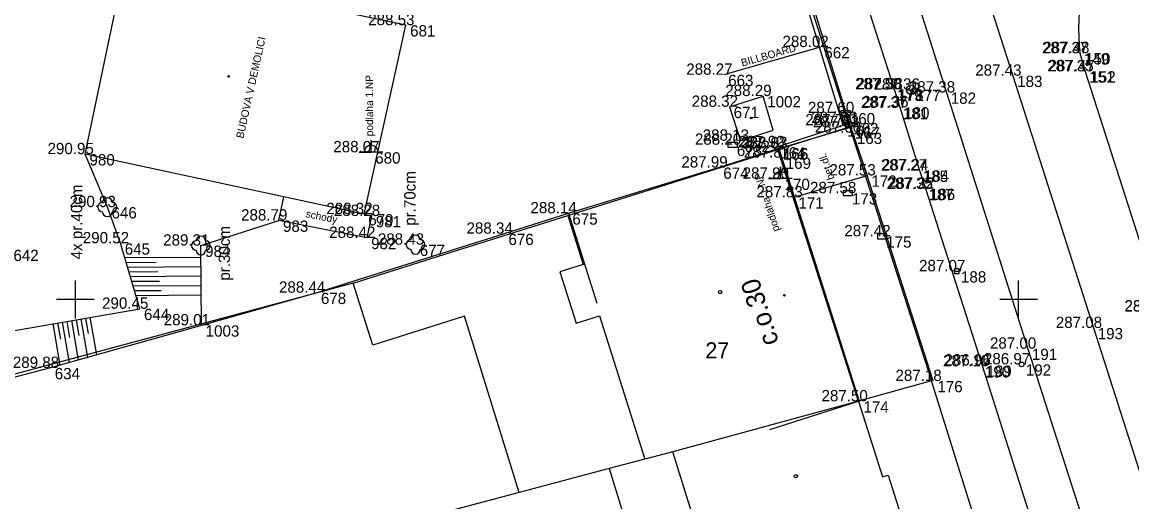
# Model space of a CAD drawing. Extents: x -599970 to -599524, y -1154772 to -1154457.
# Drawn here: x -599702.8 to -599644, y -1154660.7 to -1154635.3 of the extents above; entities that cross this region are included whole.
import ezdxf

# ---------------------------------------------------------------- set-up
doc = ezdxf.new("R2010")
doc.units = 0
for name, color, linetype in [('Z-BUDOVY', 7, 'Continuous'), ('Z-ELEKTRICKE SKRINE LAMPY', 7, 'Continuous'), ('Z-KANALIZACNI SACHTY VPUSTI', 7, 'Continuous'), ('Z-KATASTRALNI MAPA', 7, 'Continuous'), ('Z-KRIZKY CTVERCOVE SITE', 7, 'Continuous'), ('Z-ORIENTACNI A POPISNA CISLA', 7, 'Continuous'), ('Z-PLOT BETONOVY', 7, 'Continuous'), ('Z-PLOT DRATENY', 7, 'Continuous'), ('Z-PLYNOVODNI SOUPATA HUP', 7, 'Continuous'), ('Z-PODROBNE BODY', 7, 'Continuous'), ('Z-PODROBNE BODY-CISLO', 7, 'Continuous'), ('Z-PODROBNE BODY-VYSKA', 7, 'Continuous'), ('Z-POPISY OBJEKTU A ZPEVNENYCH PLOCH', 7, 'Continuous'), ('Z-PRUMERY KMENU STROMU', 7, 'Continuous'), ('Z-SCHODY', 7, 'Continuous'), ('Z-SDELOVACI VEDENI A OBJEKTY', 7, 'Continuous'), ('Z-SRAFOVANI SVAHU', 7, 'Continuous'), ('Z-STROMY ZNACKY KULTUR', 7, 'Continuous'), ('Z-TERENNI HRANY PATY', 7, 'Continuous'), ('Z-VODOROVNE ZNACENI', 7, 'Continuous'), ('Z-VODOVODNI SACHTY SOUPATA HYDRANTY', 7, 'Continuous'), ('Z-VSTUPY VJEZDY', 7, 'Continuous'), ('Z-VYSKOVE BODY', 7, 'Continuous'), ('Z-ZPEVNENE PLOCHY', 7, 'Continuous')]:
    doc.layers.add(name, color=color, linetype=linetype)

msp = doc.modelspace()

# ---------------------------------------------------------------- linework, layer by layer
at = {"layer": 'Z-BUDOVY'}
for p, q in [((-599665.33, -1154639.78), (-599663.55, -1154639.21)), ((-599662.72, -1154641.99), (-599665.88, -1154643)), ((-599665.88, -1154643), (-599673.88, -1154645.43)), ((-599672.34, -1154650.21), (-599673.84, -1154645.44)), ((-599658.45, -1154655.4), (-599663.21, -1154656.92))]:
    msp.add_line(p, q, dxfattribs=at)
for points in [[(-599684.7, -1154645.47), (-599699.48, -1154642.29), (-599697.4, -1154632.32)], [(-599684.7, -1154645.47), (-599682.48, -1154635.45), (-599697.4, -1154632.32)], [(-599664.75, -1154641.58), (-599663.01, -1154641.02), (-599663.55, -1154639.21)], [(-599665.33, -1154639.78), (-599664.75, -1154641.58)], [(-599662.72, -1154641.99), (-599658.45, -1154655.4)]]:
    msp.add_lwpolyline(points, dxfattribs=at)
at = {"layer": 'Z-ELEKTRICKE SKRINE LAMPY'}
for points in [[(-599665.41, -1154641.915), (-599664.91, -1154641.915), (-599664.91, -1154641.665), (-599665.41, -1154641.665)], [(-599659.31, -1154644.485), (-599658.81, -1154644.485), (-599658.81, -1154644.235), (-599659.31, -1154644.235)]]:
    msp.add_lwpolyline(points, close=True, dxfattribs=at)
at = {"layer": 'Z-KANALIZACNI SACHTY VPUSTI'}
msp.add_line((-599653.405, -1154648.5), (-599653.155, -1154648.5), dxfattribs=at)
msp.add_lwpolyline([(-599653.405, -1154648.625), (-599653.155, -1154648.625), (-599653.155, -1154648.375), (-599653.405, -1154648.375)], close=True, dxfattribs=at)
msp.add_circle((-599655.69, -1154638.87), 0.25, dxfattribs=at)
at = {"layer": 'Z-KATASTRALNI MAPA'}
for p, q in [((-599658.96, -1154640.84), (-599673.37, -1154595.74)), ((-599658.96, -1154640.84), (-599654.62, -1154654.32)), ((-599658.49, -1154655.39), (-599662.77, -1154642.04)), ((-599673.9, -1154645.54), (-599673.08, -1154648.14)), ((-599673.08, -1154648.14), (-599674.32, -1154648.54)), ((-599674.32, -1154648.54), (-599673.46, -1154651.26)), ((-599685.27, -1154649.13), (-599725.18, -1154659.85)), ((-599673.46, -1154651.26), (-599672.22, -1154650.87)), ((-599672.22, -1154650.87), (-599669.81, -1154658.47)), ((-599654.62, -1154654.32), (-599658.49, -1154655.39)), ((-599652.49, -1154661.15), (-599654.62, -1154654.32)), ((-599658.49, -1154655.39), (-599657.21, -1154659.4)), ((-599666.06, -1154665.39), (-599668.33, -1154658.07)), ((-599671.71, -1154658.97), (-599676.48, -1154660.24)), ((-599671.71, -1154658.97), (-599669.38, -1154666.43)), ((-599657.21, -1154659.4), (-599656.92, -1154659.31)), ((-599656.92, -1154659.31), (-599655.99, -1154662.24)), ((-599676.48, -1154660.24), (-599683.62, -1154662.13))]:
    msp.add_line(p, q, dxfattribs=at)
for points in [[(-599685.27, -1154649.13), (-599680.41, -1154647.6), (-599673.9, -1154645.54), (-599662.77, -1154642.04), (-599658.96, -1154640.84)], [(-599676.48, -1154660.24), (-599679.37, -1154650.89), (-599684.23, -1154652.42), (-599685.27, -1154649.13)], [(-599658.49, -1154655.39), (-599668.33, -1154658.07), (-599669.81, -1154658.47), (-599671.71, -1154658.97)]]:
    msp.add_lwpolyline(points, dxfattribs=at)
for centre in [(-599665.823, -1154649.61), (-599661.813, -1154659.37)]:
    msp.add_circle(centre, 0.0875, dxfattribs=at)
at = {"layer": 'Z-KRIZKY CTVERCOVE SITE'}
for p, q in [((-599700, -1154651), (-599700, -1154649)), ((-599650, -1154651), (-599650, -1154649)), ((-599699, -1154650), (-599701, -1154650)), ((-599649, -1154650), (-599651, -1154650))]:
    msp.add_line(p, q, dxfattribs=at)
at = {"layer": 'Z-PLOT BETONOVY'}
msp.add_lwpolyline([(-599673.88, -1154645.43), (-599677.27, -1154646.51), (-599687.21, -1154649.64)], dxfattribs=at)
at = {"layer": 'Z-PLOT DRATENY'}
for points in [[(-599662.86, -1154641.92), (-599659.31, -1154640.76), (-599663.16, -1154628.02), (-599666.48, -1154617.56)], [(-599659.31, -1154640.76), (-599658.99, -1154640.64), (-599658.91, -1154640.86), (-599658.8, -1154641.15)], [(-599654.53, -1154654.32), (-599658.03, -1154643.42)], [(-599687.21, -1154649.64), (-599693.32, -1154651.37), (-599701.32, -1154653.63), (-599705.77, -1154654.79), (-599712.31, -1154656.66), (-599717.12, -1154657.86), (-599722.32, -1154659.26), (-599725.96, -1154660.31)]]:
    msp.add_lwpolyline(points, dxfattribs=at)
at = {"layer": 'Z-PLYNOVODNI SOUPATA HUP'}
msp.add_lwpolyline([(-599657.49, -1154646.775), (-599656.99, -1154646.775), (-599656.99, -1154646.525), (-599657.49, -1154646.525)], close=True, dxfattribs=at)
at = {"layer": 'Z-PODROBNE BODY'}
for p, q in [((-599682.48, -1154635.45), (-599682.48, -1154635.45)), ((-599660.52, -1154636.61), (-599660.52, -1154636.61)), ((-599646.76, -1154636.94), (-599646.76, -1154636.94)), ((-599646.7, -1154636.93), (-599646.7, -1154636.93)), ((-599665.62, -1154638.08), (-599665.62, -1154638.08)), ((-599650.3, -1154638.13), (-599650.3, -1154638.13)), ((-599646.48, -1154637.9), (-599646.48, -1154637.9)), ((-599646.42, -1154637.89), (-599646.42, -1154637.89)), ((-599656.67, -1154638.85), (-599656.67, -1154638.85)), ((-599656.6, -1154638.85), (-599656.6, -1154638.85)), ((-599655.69, -1154638.87), (-599655.69, -1154638.87)), ((-599663.55, -1154639.21), (-599663.55, -1154639.21)), ((-599653.82, -1154639.02), (-599653.82, -1154639.02)), ((-599665.33, -1154639.78), (-599665.33, -1154639.78)), ((-599656.36, -1154639.84), (-599656.36, -1154639.84)), ((-599656.29, -1154639.8), (-599656.29, -1154639.8)), ((-599659.17, -1154640.11), (-599659.17, -1154640.11)), ((-599658.99, -1154640.64), (-599658.99, -1154640.64)), ((-599659.31, -1154640.76), (-599659.31, -1154640.76)), ((-599658.91, -1154640.86), (-599658.91, -1154640.86)), ((-599658.8, -1154641.15), (-599658.8, -1154641.15)), ((-599665.16, -1154641.79), (-599665.16, -1154641.79)), ((-599664.75, -1154641.58), (-599664.75, -1154641.58)), ((-599699.48, -1154642.29), (-599699.48, -1154642.29)), ((-599684.33, -1154642.19), (-599684.33, -1154642.19)), ((-599662.86, -1154641.92), (-599662.86, -1154641.92)), ((-599662.72, -1154641.99), (-599662.72, -1154641.99)), ((-599662.71, -1154641.97), (-599662.71, -1154641.97)), ((-599665.88, -1154643), (-599665.88, -1154643)), ((-599662.57, -1154642.47), (-599662.57, -1154642.47)), ((-599662.63, -1154643.59), (-599662.63, -1154643.59)), ((-599658.03, -1154643.42), (-599658.03, -1154643.42)), ((-599655.3, -1154643.16), (-599655.3, -1154643.16)), ((-599655.25, -1154643.15), (-599655.25, -1154643.15)), ((-599655, -1154644.14), (-599655, -1154644.14)), ((-599654.93, -1154644.12), (-599654.93, -1154644.12)), ((-599661.9, -1154644.58), (-599661.9, -1154644.58)), ((-599659.06, -1154644.36), (-599659.06, -1154644.36)), ((-599698.31, -1154645.1), (-599698.31, -1154645.1)), ((-599689.22, -1154645.81), (-599689.22, -1154645.81)), ((-599684.7, -1154645.47), (-599684.7, -1154645.47)), ((-599684.3, -1154645.57), (-599684.3, -1154645.57)), ((-599673.88, -1154645.43), (-599673.88, -1154645.43)), ((-599677.27, -1154646.51), (-599677.27, -1154646.51)), ((-599697.61, -1154647.02), (-599697.61, -1154647.02)), ((-599693.35, -1154647.14), (-599693.35, -1154647.14)), ((-599684.55, -1154646.73), (-599684.55, -1154646.73)), ((-599681.97, -1154647.09), (-599681.97, -1154647.09)), ((-599657.24, -1154646.65), (-599657.24, -1154646.65)), ((-599653.28, -1154648.5), (-599653.28, -1154648.5)), ((-599687.21, -1154649.64), (-599687.21, -1154649.64)), ((-599696.59, -1154650.49), (-599696.59, -1154650.49)), ((-599693.32, -1154651.37), (-599693.32, -1154651.37)), ((-599646.03, -1154651.51), (-599646.03, -1154651.51)), ((-599649.52, -1154652.61), (-599649.52, -1154652.61)), ((-599652.01, -1154653.54), (-599652.01, -1154653.54)), ((-599651.93, -1154653.5), (-599651.93, -1154653.5)), ((-599649.84, -1154653.44), (-599649.84, -1154653.44)), ((-599701.32, -1154653.63), (-599701.32, -1154653.63)), ((-599654.53, -1154654.32), (-599654.53, -1154654.32)), ((-599658.45, -1154655.4), (-599658.45, -1154655.4))]:
    msp.add_line(p, q, dxfattribs=at)
at = {"layer": 'Z-SCHODY'}
msp.add_lwpolyline([(-599684.7, -1154645.47), (-599684.3, -1154645.57), (-599684.55, -1154646.73), (-599689.22, -1154645.81), (-599688.96, -1154644.55)], dxfattribs=at)
for centre in [(-599691.88, -1154638.17), (-599664.18, -1154640.37), (-599662.42, -1154649.78)]:
    msp.add_circle(centre, 0.0438, dxfattribs=at)
at = {"layer": 'Z-SDELOVACI VEDENI A OBJEKTY'}
msp.add_lwpolyline([(-599659.42, -1154640.235), (-599658.92, -1154640.235), (-599658.92, -1154639.985), (-599659.42, -1154639.985)], close=True, dxfattribs=at)
at = {"layer": 'Z-SRAFOVANI SVAHU'}
for points in [[(-599697.39, -1154647.78), (-599693.35, -1154647.75)], [(-599697.31, -1154648.03), (-599695.72, -1154648.02)], [(-599697.24, -1154648.28), (-599693.34, -1154648.25)], [(-599697.17, -1154648.53), (-599695.63, -1154648.52)], [(-599697.09, -1154648.78), (-599693.34, -1154648.75)], [(-599697.02, -1154649.03), (-599695.55, -1154649.02)], [(-599696.95, -1154649.28), (-599693.33, -1154649.25)], [(-599696.87, -1154649.53), (-599695.46, -1154649.52)], [(-599696.8, -1154649.78), (-599693.33, -1154649.75)], [(-599700.95, -1154651.24), (-599700.8, -1154652.11)], [(-599700.71, -1154651.2), (-599700.33, -1154653.35)], [(-599700.46, -1154651.16), (-599700.31, -1154652.01)], [(-599700.21, -1154651.11), (-599699.85, -1154653.21)], [(-599699.97, -1154651.07), (-599699.82, -1154651.9)], [(-599699.72, -1154651.03), (-599699.37, -1154653.08)], [(-599699.47, -1154650.99), (-599699.33, -1154651.8)], [(-599699.23, -1154650.94), (-599698.88, -1154652.94)], [(-599701.2, -1154651.28), (-599700.82, -1154653.49)]]:
    msp.add_lwpolyline(points, dxfattribs=at)
at = {"layer": 'Z-STROMY ZNACKY KULTUR'}
for centre in [(-599698.31, -1154645.1), (-599693.35, -1154647.14), (-599681.97, -1154647.09)]:
    msp.add_circle(centre, 0.00025, dxfattribs=at)
for centre, start, end in [((-599698.31, -1154644.85), 0, 179.99999), ((-599698.56, -1154645.1), 89.99999, 269.99999), ((-599698.31, -1154645.35), 179.99999, 359.99999), ((-599698.06, -1154645.1), 270, 89.99999), ((-599693.6, -1154647.14), 89.99999, 269.99999), ((-599693.35, -1154646.89), 0, 179.99999), ((-599693.1, -1154647.14), 270, 89.99999), ((-599682.22, -1154647.09), 89.99999, 269.99999), ((-599681.97, -1154646.84), 0, 179.99999), ((-599681.72, -1154647.09), 270, 89.99999), ((-599693.35, -1154647.39), 179.99999, 359.99999), ((-599681.97, -1154647.34), 179.99999, 359.99999)]:
    msp.add_arc(centre, 0.25, start, end, dxfattribs=at)
at = {"layer": 'Z-TERENNI HRANY PATY'}
for points in [[(-599706.85, -1154650.78), (-599704.37, -1154651.83), (-599696.59, -1154650.49), (-599697.61, -1154647.02), (-599698.31, -1154645.1), (-599699.48, -1154642.29)], [(-599693.32, -1154651.37), (-599693.35, -1154647.14), (-599689.22, -1154645.81)]]:
    msp.add_lwpolyline(points, dxfattribs=at)
at = {"layer": 'Z-VODOROVNE ZNACENI'}
for points in [[(-599694.02, -1154499.99), (-599689.54, -1154514.32), (-599685.46, -1154527.42), (-599683.24, -1154534.53), (-599677.91, -1154551.43), (-599673.26, -1154566.04), (-599670.15, -1154575.91), (-599664.69, -1154593.08), (-599661.63, -1154602.65), (-599657.71, -1154615.01), (-599654.33, -1154625.58), (-599650.3, -1154638.13), (-599646.03, -1154651.51), (-599641.58, -1154665.41), (-599629.85, -1154702.06), (-599625.38, -1154716.06)], [(-599697.63, -1154501.15), (-599693.46, -1154514.34), (-599689.12, -1154528.02), (-599685.9, -1154538.22), (-599681.17, -1154553.13), (-599676.65, -1154567.39), (-599673.59, -1154577), (-599671.31, -1154584.14), (-599668.11, -1154594.2), (-599666.34, -1154599.75), (-599661.15, -1154616.02), (-599657.79, -1154626.57), (-599653.82, -1154639.02), (-599649.52, -1154652.61), (-599645.03, -1154666.6), (-599639.28, -1154684.62), (-599637.35, -1154690.63), (-599633.4, -1154703.39)]]:
    msp.add_lwpolyline(points, dxfattribs=at)
at = {"layer": 'Z-VODOVODNI SACHTY SOUPATA HYDRANTY'}
msp.add_circle((-599649.84, -1154653.44), 0.125, dxfattribs=at)
at = {"layer": 'Z-VSTUPY VJEZDY'}
for points in [[(-599658.8, -1154641.15), (-599658.03, -1154643.42)], [(-599662.57, -1154642.47), (-599661.9, -1154644.58)]]:
    msp.add_lwpolyline(points, dxfattribs=at)
at = {"layer": 'Z-VYSKOVE BODY'}
for p, q in [((-599684.33, -1154641.565), (-599684.33, -1154641.815)), ((-599684.33, -1154641.815), (-599684.33, -1154641.565)), ((-599684.33, -1154642.19), (-599684.33, -1154641.565)), ((-599684.33, -1154641.565), (-599684.33, -1154641.815)), ((-599683.705, -1154642.19), (-599684.955, -1154642.19)), ((-599684.955, -1154642.19), (-599684.33, -1154642.19)), ((-599683.705, -1154642.19), (-599684.33, -1154642.19)), ((-599662.63, -1154642.965), (-599662.63, -1154643.215)), ((-599662.63, -1154643.215), (-599662.63, -1154642.965)), ((-599662.63, -1154643.59), (-599662.63, -1154642.965)), ((-599662.63, -1154642.965), (-599662.63, -1154643.215)), ((-599662.005, -1154643.59), (-599663.255, -1154643.59)), ((-599663.255, -1154643.59), (-599662.63, -1154643.59)), ((-599662.005, -1154643.59), (-599662.63, -1154643.59))]:
    msp.add_line(p, q, dxfattribs=at)
for centre, start, end in [((-599684.33, -1154642.19), 89.99999, 179.99999), ((-599684.33, -1154642.19), 0, 89.99999), ((-599662.63, -1154643.59), 89.99999, 179.99999), ((-599662.63, -1154643.59), 0, 89.99999)]:
    msp.add_arc(centre, 0.375, start, end, dxfattribs=at)
at = {"layer": 'Z-ZPEVNENE PLOCHY'}
for points in [[(-599672.4, -1154589.48), (-599670.73, -1154594.81), (-599667.36, -1154605.26), (-599665.4, -1154611.41), (-599665.09, -1154612.38), (-599663.59, -1154616.97), (-599663.32, -1154617.94), (-599660.4, -1154627.02), (-599656.6, -1154638.85), (-599656.29, -1154639.8), (-599655.25, -1154643.15), (-599654.93, -1154644.12), (-599651.93, -1154653.5), (-599647.41, -1154667.76), (-599641.59, -1154686.01), (-599637.45, -1154690.75), (-599637.27, -1154691.05), (-599637.22, -1154691.51), (-599636.57, -1154701.7), (-599631.18, -1154718.34)], [(-599666.48, -1154617.56), (-599666.25, -1154617.44), (-599662.9, -1154627.92), (-599658.99, -1154640.64)], [(-599660.52, -1154636.61), (-599665.62, -1154638.08)], [(-599646.76, -1154636.94), (-599646.48, -1154637.9), (-599642.39, -1154650.64), (-599638.05, -1154664.15), (-599632.16, -1154682.64), (-599630.36, -1154688.43), (-599622.63, -1154699.78), (-599618.24, -1154713.84)], [(-599662.72, -1154641.99), (-599658.91, -1154640.86)], [(-599661.9, -1154644.58), (-599658.03, -1154643.42)]]:
    msp.add_lwpolyline(points, dxfattribs=at)
msp.add_arc((-599631.948, -1154635.616), 14.871, 158.14304, 185.10595, dxfattribs=at)

# ---------------------------------------------------------------- texts
at = {"layer": 'Z-KATASTRALNI MAPA'}
msp.add_text('27', height=0.85, dxfattribs=at).set_placement((-599666.609, -1154653.12))
at = {"layer": 'Z-ORIENTACNI A POPISNA CISLA'}
msp.add_text('c.o.30', height=1, rotation=107.66247, dxfattribs=at).set_placement((-599662.7, -1154652.27))
at = {"layer": 'Z-PODROBNE BODY-CISLO'}
for s, p in [(' 681', (-599682.48, -1154636.05)), (' 662', (-599660.52, -1154637.21)), (' 149', (-599646.76, -1154637.54)), (' 150', (-599646.7, -1154637.53)), (' 663', (-599665.62, -1154638.68)), (' 183', (-599650.3, -1154638.73)), (' 151', (-599646.48, -1154638.5)), (' 152', (-599646.42, -1154638.49)), (' 179', (-599656.67, -1154639.45)), (' 178', (-599656.6, -1154639.45)), (' 177', (-599655.69, -1154639.47)), (' 1002', (-599663.55, -1154639.81)), (' 182', (-599653.82, -1154639.62)), (' 671', (-599665.33, -1154640.38)), (' 181', (-599656.36, -1154640.44)), (' 180', (-599656.29, -1154640.4)), (' 160', (-599659.17, -1154640.71)), (' 162', (-599658.99, -1154641.24)), (' 161', (-599659.31, -1154641.36)), (' 167', (-599658.91, -1154641.46)), (' 163', (-599658.8, -1154641.75)), (' 673', (-599665.16, -1154642.39)), (' 672', (-599664.75, -1154642.18)), (' 980', (-599699.48, -1154642.89)), (' 680', (-599684.33, -1154642.79)), (' 164', (-599662.86, -1154642.52)), (' 165', (-599662.72, -1154642.59)), (' 166', (-599662.71, -1154642.57)), (' 674', (-599665.88, -1154643.6)), (' 169', (-599662.57, -1154643.07)), (' 170', (-599662.63, -1154644.19)), (' 172', (-599658.03, -1154644.02)), (' 185', (-599655.3, -1154643.76)), (' 184', (-599655.25, -1154643.75)), (' 187', (-599655, -1154644.74)), (' 186', (-599654.93, -1154644.72)), (' 171', (-599661.9, -1154645.18)), (' 173', (-599659.06, -1154644.96)), (' 646', (-599698.31, -1154645.7)), (' 983', (-599689.22, -1154646.41)), (' 679', (-599684.7, -1154646.07)), (' 981', (-599684.3, -1154646.17)), (' 675', (-599673.88, -1154646.03)), (' 676', (-599677.27, -1154647.11)), (' 645', (-599697.61, -1154647.62)), (' 984', (-599693.35, -1154647.74)), (' 982', (-599684.55, -1154647.33)), (' 677', (-599681.97, -1154647.69)), (' 175', (-599657.24, -1154647.25)), (' 642', (-599703.51, -1154647.96)), (' 188', (-599653.28, -1154649.1)), (' 678', (-599687.21, -1154650.24)), (' 644', (-599696.59, -1154651.09)), (' 1003', (-599693.32, -1154651.97)), (' 193', (-599646.03, -1154652.11)), (' 191', (-599649.52, -1154653.21)), (' 634', (-599701.32, -1154654.23)), (' 190', (-599652.01, -1154654.14)), (' 189', (-599651.93, -1154654.1)), (' 192', (-599649.84, -1154654.04)), (' 176', (-599654.53, -1154654.92)), (' 174', (-599658.45, -1154656))]:
    msp.add_text(s, height=0.6, dxfattribs=at).set_placement(p)
at = {"layer": 'Z-PODROBNE BODY-VYSKA'}
for s, p in [('288.53 ', (-599684.48, -1154635.45)), ('288.02 ', (-599662.52, -1154636.61)), ('287.37 ', (-599648.76, -1154636.94)), ('287.48 ', (-599648.7, -1154636.93)), ('288.27 ', (-599667.62, -1154638.08)), ('287.43 ', (-599652.3, -1154638.13)), ('287.35 ', (-599648.48, -1154637.9)), ('287.47 ', (-599648.42, -1154637.89)), ('287.50 ', (-599658.67, -1154638.85)), ('287.38 ', (-599658.6, -1154638.85)), ('287.36 ', (-599657.69, -1154638.87)), ('288.29 ', (-599665.55, -1154639.21)), ('287.38 ', (-599655.82, -1154639.02)), ('288.32 ', (-599667.33, -1154639.78)), ('287.60 ', (-599661.17, -1154640.11)), ('287.37 ', (-599658.36, -1154639.84)), ('287.36 ', (-599658.29, -1154639.8)), ('287.63 ', (-599660.99, -1154640.64)), ('287.79 ', (-599661.31, -1154640.76)), ('287.63 ', (-599660.91, -1154640.86)), ('287.60 ', (-599660.8, -1154641.15)), ('288.20 ', (-599667.16, -1154641.79)), ('288.13 ', (-599666.75, -1154641.58)), ('290.95 ', (-599701.48, -1154642.29)), ('288.07 ', (-599686.33, -1154642.19)), ('287.92 ', (-599664.86, -1154641.92)), ('287.87 ', (-599664.72, -1154641.99)), ('288.03 ', (-599664.71, -1154641.97)), ('287.87 ', (-599664.57, -1154642.47)), ('287.99 ', (-599667.88, -1154643)), ('287.90 ', (-599664.63, -1154643.59)), ('287.53 ', (-599660.03, -1154643.42)), ('287.27 ', (-599657.3, -1154643.16)), ('287.24 ', (-599657.25, -1154643.15)), ('287.35 ', (-599657, -1154644.14)), ('287.22 ', (-599656.93, -1154644.12)), ('287.83 ', (-599663.9, -1154644.58)), ('287.58 ', (-599661.06, -1154644.36)), ('290.93 ', (-599700.31, -1154645.1)), ('288.79 ', (-599691.22, -1154645.81)), ('288.32 ', (-599686.7, -1154645.47)), ('288.28 ', (-599686.3, -1154645.57)), ('288.14 ', (-599675.88, -1154645.43)), ('288.34 ', (-599679.27, -1154646.51)), ('290.52 ', (-599699.61, -1154647.02)), ('289.31 ', (-599695.35, -1154647.14)), ('288.42 ', (-599686.55, -1154646.73)), ('288.43 ', (-599683.97, -1154647.09)), ('287.42 ', (-599659.24, -1154646.65)), ('287.07 ', (-599655.28, -1154648.5)), ('288.44 ', (-599689.21, -1154649.64)), ('290.45 ', (-599698.59, -1154650.49)), ('287.13 ', (-599644.39, -1154650.63)), ('287.01 ', (-599644.39, -1154650.64)), ('289.01 ', (-599695.32, -1154651.37)), ('287.08 ', (-599648.03, -1154651.51)), ('287.00 ', (-599651.52, -1154652.61)), ('289.88 ', (-599703.32, -1154653.63)), ('287.10 ', (-599654.01, -1154653.54)), ('286.96 ', (-599653.93, -1154653.5)), ('286.97 ', (-599651.84, -1154653.44)), ('287.18 ', (-599656.53, -1154654.32)), ('287.50 ', (-599660.45, -1154655.4))]:
    msp.add_text(s, height=0.6, dxfattribs=at).set_placement(p)
at = {"layer": 'Z-POPISY OBJEKTU A ZPEVNENYCH PLOCH'}
for s, rotation, p in [('BUDOVA V DEMOLICI', 77.50752, (-599691.1, -1154641.48)), ('BILLBOARD', 16.07885, (-599664.65, -1154637.65)), ('bet.dl.', 108.7373, (-599659.76, -1154643.58)), ('schody', 348.85532, (-599687.82, -1154645.63))]:
    msp.add_text(s, height=0.4, rotation=rotation, dxfattribs=at).set_placement(p)
at = {"layer": 'Z-PRUMERY KMENU STROMU'}
for s, p in [('pr.70cm', (-599681.97, -1154646.09)), ('4x pr.40cm', (-599699.64, -1154647.87)), ('pr.30cm', (-599691.81, -1154649))]:
    msp.add_text(s, height=0.6, rotation=90, dxfattribs=at).set_placement(p)
at = {"layer": 'Z-VYSKOVE BODY'}
for rotation, p in [(90, (-599684.22, -1154641.34)), (107.66247, (-599662.66, -1154646.33))]:
    msp.add_text('podlaha 1.NP', height=0.4, rotation=rotation, dxfattribs=at).set_placement(p)

doc.saveas('drawing.dxf')
